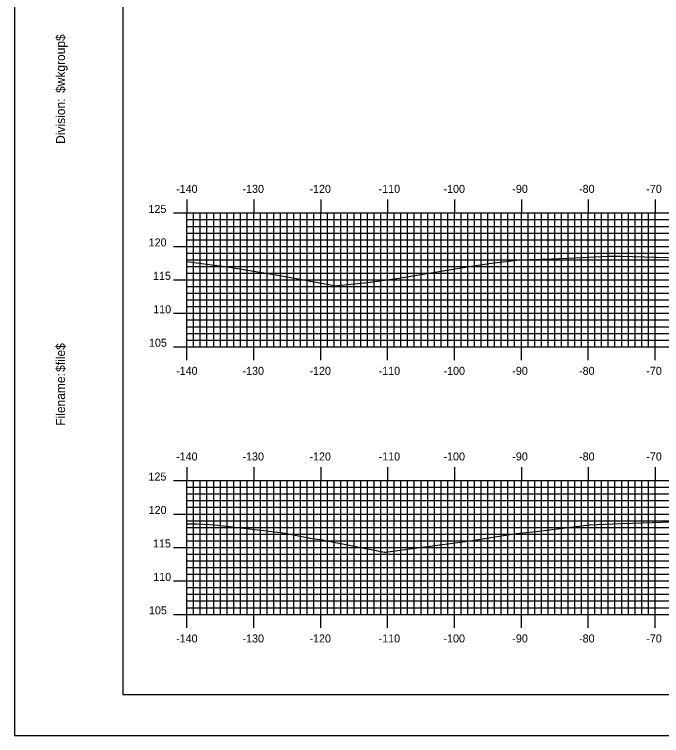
# Model space of a CAD drawing. Extents: x 844930 to 845273, y 363538 to 363758.
# Drawn here: x 844929.7 to 845026.4, y 363537.6 to 363645.4 of the extents above; entities that cross this region are included whole.
import ezdxf

# ---------------------------------------------------------------- set-up
doc = ezdxf.new("R2010")
doc.units = 0
for name, color, linetype in [('BORDER', 7, 'Continuous'), ('H_V ANNOTATION', 7, 'Continuous'), ('M_Roadway_Centerline', 7, 'Continuous'), ('MAJOR', 7, 'Continuous'), ('MINOR', 7, 'Continuous'), ('PLOT BOUNDARY', 7, 'Continuous'), ('S_Roadway_Centerline', 7, 'Continuous')]:
    doc.layers.add(name, color=color, linetype=linetype)

msp = doc.modelspace()

# ---------------------------------------------------------------- linework, layer by layer
at = {"layer": 'BORDER'}
msp.add_lwpolyline([(844945.88, 363543.72), (845265.88, 363543.72), (845265.88, 363753.72), (844945.88, 363753.72)], close=True, dxfattribs=at)
at = {"layer": 'MAJOR'}
for p, q in [((844955.48, 363617.73), (844955.48, 363615.72)), ((844965.48, 363617.73), (844965.48, 363615.72)), ((844975.48, 363617.73), (844975.48, 363615.72)), ((844985.48, 363617.73), (844985.48, 363615.72)), ((844995.48, 363617.73), (844995.48, 363615.72)), ((845005.48, 363617.73), (845005.48, 363615.72)), ((845015.48, 363617.73), (845015.48, 363615.72)), ((845025.48, 363617.73), (845025.48, 363615.72)), ((844953.47, 363615.72), (844955.48, 363615.72)), ((844955.48, 363615.72), (845235.48, 363615.72)), ((844955.48, 363595.72), (844955.48, 363615.72)), ((844955.48, 363595.72), (844955.48, 363615.72)), ((844955.48, 363615.72), (845235.48, 363615.72)), ((844965.48, 363595.72), (844965.48, 363615.72)), ((844975.48, 363595.72), (844975.48, 363615.72)), ((844985.48, 363595.72), (844985.48, 363615.72)), ((844995.48, 363595.72), (844995.48, 363615.72)), ((845005.48, 363595.72), (845005.48, 363615.72)), ((845015.48, 363595.72), (845015.48, 363615.72)), ((845025.48, 363595.72), (845025.48, 363615.72)), ((844953.47, 363610.72), (844955.48, 363610.72)), ((844955.48, 363610.72), (845235.48, 363610.72)), ((844953.47, 363605.72), (844955.48, 363605.72)), ((844955.48, 363605.72), (845235.48, 363605.72)), ((844953.47, 363600.72), (844955.48, 363600.72)), ((844955.48, 363600.72), (845235.48, 363600.72)), ((844953.47, 363595.72), (844955.48, 363595.72)), ((844955.48, 363595.72), (845235.48, 363595.72)), ((844955.48, 363595.72), (845235.48, 363595.72)), ((844955.48, 363593.72), (844955.48, 363595.72)), ((844965.48, 363593.72), (844965.48, 363595.72)), ((844975.48, 363593.72), (844975.48, 363595.72)), ((844985.48, 363593.72), (844985.48, 363595.72)), ((844995.48, 363593.72), (844995.48, 363595.72)), ((845005.48, 363593.72), (845005.48, 363595.72)), ((845015.48, 363593.72), (845015.48, 363595.72)), ((845025.48, 363593.72), (845025.48, 363595.72)), ((844955.48, 363577.73), (844955.48, 363575.72)), ((844965.48, 363577.73), (844965.48, 363575.72)), ((844975.48, 363577.73), (844975.48, 363575.72)), ((844985.48, 363577.73), (844985.48, 363575.72)), ((844995.48, 363577.73), (844995.48, 363575.72)), ((845005.48, 363577.73), (845005.48, 363575.72)), ((845015.48, 363577.73), (845015.48, 363575.72)), ((845025.48, 363577.73), (845025.48, 363575.72)), ((844953.47, 363575.72), (844955.48, 363575.72)), ((844955.48, 363575.72), (845235.48, 363575.72)), ((844955.48, 363555.72), (844955.48, 363575.72)), ((844955.48, 363555.72), (844955.48, 363575.72)), ((844955.48, 363575.72), (845235.48, 363575.72)), ((844965.48, 363555.72), (844965.48, 363575.72)), ((844975.48, 363555.72), (844975.48, 363575.72)), ((844985.48, 363555.72), (844985.48, 363575.72)), ((844995.48, 363555.72), (844995.48, 363575.72)), ((845005.48, 363555.72), (845005.48, 363575.72)), ((845015.48, 363555.72), (845015.48, 363575.72)), ((845025.48, 363555.72), (845025.48, 363575.72)), ((844953.47, 363570.72), (844955.48, 363570.72)), ((844955.48, 363570.72), (845235.48, 363570.72)), ((844953.47, 363565.72), (844955.48, 363565.72)), ((844955.48, 363565.72), (845235.48, 363565.72)), ((844953.47, 363560.72), (844955.48, 363560.72)), ((844955.48, 363560.72), (845235.48, 363560.72)), ((844953.47, 363555.72), (844955.48, 363555.72)), ((844955.48, 363555.72), (845235.48, 363555.72)), ((844955.48, 363555.72), (845235.48, 363555.72)), ((844955.48, 363553.72), (844955.48, 363555.72)), ((844965.48, 363553.72), (844965.48, 363555.72)), ((844975.48, 363553.72), (844975.48, 363555.72)), ((844985.48, 363553.72), (844985.48, 363555.72)), ((844995.48, 363553.72), (844995.48, 363555.72)), ((845005.48, 363553.72), (845005.48, 363555.72)), ((845015.48, 363553.72), (845015.48, 363555.72)), ((845025.48, 363553.72), (845025.48, 363555.72))]:
    msp.add_line(p, q, dxfattribs=at)
at = {"layer": 'MINOR'}
for p, q in [((844956.48, 363595.72), (844956.48, 363615.72)), ((844957.48, 363595.72), (844957.48, 363615.72)), ((844958.48, 363595.72), (844958.48, 363615.72)), ((844959.48, 363595.72), (844959.48, 363615.72)), ((844960.48, 363595.72), (844960.48, 363615.72)), ((844961.48, 363595.72), (844961.48, 363615.72)), ((844962.48, 363595.72), (844962.48, 363615.72)), ((844963.48, 363595.72), (844963.48, 363615.72)), ((844964.48, 363595.72), (844964.48, 363615.72)), ((844966.48, 363595.72), (844966.48, 363615.72)), ((844967.48, 363595.72), (844967.48, 363615.72)), ((844968.48, 363595.72), (844968.48, 363615.72)), ((844969.48, 363595.72), (844969.48, 363615.72)), ((844970.48, 363595.72), (844970.48, 363615.72)), ((844971.48, 363595.72), (844971.48, 363615.72)), ((844972.48, 363595.72), (844972.48, 363615.72)), ((844973.48, 363595.72), (844973.48, 363615.72)), ((844974.48, 363595.72), (844974.48, 363615.72)), ((844976.48, 363595.72), (844976.48, 363615.72)), ((844977.48, 363595.72), (844977.48, 363615.72)), ((844978.48, 363595.72), (844978.48, 363615.72)), ((844979.48, 363595.72), (844979.48, 363615.72)), ((844980.48, 363595.72), (844980.48, 363615.72)), ((844981.48, 363595.72), (844981.48, 363615.72)), ((844982.48, 363595.72), (844982.48, 363615.72)), ((844983.48, 363595.72), (844983.48, 363615.72)), ((844984.48, 363595.72), (844984.48, 363615.72)), ((844986.48, 363595.72), (844986.48, 363615.72)), ((844987.48, 363595.72), (844987.48, 363615.72)), ((844988.48, 363595.72), (844988.48, 363615.72)), ((844989.48, 363595.72), (844989.48, 363615.72)), ((844990.48, 363595.72), (844990.48, 363615.72)), ((844991.48, 363595.72), (844991.48, 363615.72)), ((844992.48, 363595.72), (844992.48, 363615.72)), ((844993.48, 363595.72), (844993.48, 363615.72)), ((844994.48, 363595.72), (844994.48, 363615.72)), ((844996.48, 363595.72), (844996.48, 363615.72)), ((844997.48, 363595.72), (844997.48, 363615.72)), ((844998.48, 363595.72), (844998.48, 363615.72)), ((844999.48, 363595.72), (844999.48, 363615.72)), ((845000.48, 363595.72), (845000.48, 363615.72)), ((845001.48, 363595.72), (845001.48, 363615.72)), ((845002.48, 363595.72), (845002.48, 363615.72)), ((845003.48, 363595.72), (845003.48, 363615.72)), ((845004.48, 363595.72), (845004.48, 363615.72)), ((845006.48, 363595.72), (845006.48, 363615.72)), ((845007.48, 363595.72), (845007.48, 363615.72)), ((845008.48, 363595.72), (845008.48, 363615.72)), ((845009.48, 363595.72), (845009.48, 363615.72)), ((845010.48, 363595.72), (845010.48, 363615.72)), ((845011.48, 363595.72), (845011.48, 363615.72)), ((845012.48, 363595.72), (845012.48, 363615.72)), ((845013.48, 363595.72), (845013.48, 363615.72)), ((845014.48, 363595.72), (845014.48, 363615.72)), ((845016.48, 363595.72), (845016.48, 363615.72)), ((845017.48, 363595.72), (845017.48, 363615.72)), ((845018.48, 363595.72), (845018.48, 363615.72)), ((845019.48, 363595.72), (845019.48, 363615.72)), ((845020.48, 363595.72), (845020.48, 363615.72)), ((845021.48, 363595.72), (845021.48, 363615.72)), ((845022.48, 363595.72), (845022.48, 363615.72)), ((845023.48, 363595.72), (845023.48, 363615.72)), ((845024.48, 363595.72), (845024.48, 363615.72)), ((844955.48, 363614.72), (845235.48, 363614.72)), ((844955.48, 363614.72), (844957.48, 363614.72)), ((844955.48, 363613.72), (845235.48, 363613.72)), ((844955.48, 363613.72), (844957.48, 363613.72)), ((844955.48, 363612.72), (845235.48, 363612.72)), ((844955.48, 363612.72), (844957.48, 363612.72)), ((844955.48, 363611.72), (845235.48, 363611.72)), ((844955.48, 363611.72), (844957.48, 363611.72)), ((844955.48, 363609.72), (845235.48, 363609.72)), ((844955.48, 363609.72), (844957.48, 363609.72)), ((844955.48, 363608.72), (845235.48, 363608.72)), ((844955.48, 363608.72), (844957.48, 363608.72)), ((844955.48, 363607.72), (845235.48, 363607.72)), ((844955.48, 363607.72), (844957.48, 363607.72)), ((844955.48, 363606.72), (845235.48, 363606.72)), ((844955.48, 363606.72), (844957.48, 363606.72)), ((844955.48, 363604.72), (845235.48, 363604.72)), ((844955.48, 363604.72), (844957.48, 363604.72)), ((844955.48, 363603.72), (845235.48, 363603.72)), ((844955.48, 363603.72), (844957.48, 363603.72)), ((844955.48, 363602.72), (845235.48, 363602.72)), ((844955.48, 363602.72), (844957.48, 363602.72)), ((844955.48, 363601.72), (845235.48, 363601.72)), ((844955.48, 363601.72), (844957.48, 363601.72)), ((844955.48, 363599.72), (845235.48, 363599.72)), ((844955.48, 363599.72), (844957.48, 363599.72)), ((844955.48, 363598.72), (845235.48, 363598.72)), ((844955.48, 363598.72), (844957.48, 363598.72)), ((844955.48, 363597.72), (845235.48, 363597.72)), ((844955.48, 363597.72), (844957.48, 363597.72)), ((844955.48, 363596.72), (845235.48, 363596.72)), ((844955.48, 363596.72), (844957.48, 363596.72)), ((844956.48, 363555.72), (844956.48, 363575.72)), ((844957.48, 363555.72), (844957.48, 363575.72)), ((844958.48, 363555.72), (844958.48, 363575.72)), ((844959.48, 363555.72), (844959.48, 363575.72)), ((844960.48, 363555.72), (844960.48, 363575.72)), ((844961.48, 363555.72), (844961.48, 363575.72)), ((844962.48, 363555.72), (844962.48, 363575.72)), ((844963.48, 363555.72), (844963.48, 363575.72)), ((844964.48, 363555.72), (844964.48, 363575.72)), ((844966.48, 363555.72), (844966.48, 363575.72)), ((844967.48, 363555.72), (844967.48, 363575.72)), ((844968.48, 363555.72), (844968.48, 363575.72)), ((844969.48, 363555.72), (844969.48, 363575.72)), ((844970.48, 363555.72), (844970.48, 363575.72)), ((844971.48, 363555.72), (844971.48, 363575.72)), ((844972.48, 363555.72), (844972.48, 363575.72)), ((844973.48, 363555.72), (844973.48, 363575.72)), ((844974.48, 363555.72), (844974.48, 363575.72)), ((844976.48, 363555.72), (844976.48, 363575.72)), ((844977.48, 363555.72), (844977.48, 363575.72)), ((844978.48, 363555.72), (844978.48, 363575.72)), ((844979.48, 363555.72), (844979.48, 363575.72)), ((844980.48, 363555.72), (844980.48, 363575.72)), ((844981.48, 363555.72), (844981.48, 363575.72)), ((844982.48, 363555.72), (844982.48, 363575.72)), ((844983.48, 363555.72), (844983.48, 363575.72)), ((844984.48, 363555.72), (844984.48, 363575.72)), ((844986.48, 363555.72), (844986.48, 363575.72)), ((844987.48, 363555.72), (844987.48, 363575.72)), ((844988.48, 363555.72), (844988.48, 363575.72)), ((844989.48, 363555.72), (844989.48, 363575.72)), ((844990.48, 363555.72), (844990.48, 363575.72)), ((844991.48, 363555.72), (844991.48, 363575.72)), ((844992.48, 363555.72), (844992.48, 363575.72)), ((844993.48, 363555.72), (844993.48, 363575.72)), ((844994.48, 363555.72), (844994.48, 363575.72)), ((844996.48, 363555.72), (844996.48, 363575.72)), ((844997.48, 363555.72), (844997.48, 363575.72)), ((844998.48, 363555.72), (844998.48, 363575.72)), ((844999.48, 363555.72), (844999.48, 363575.72)), ((845000.48, 363555.72), (845000.48, 363575.72)), ((845001.48, 363555.72), (845001.48, 363575.72)), ((845002.48, 363555.72), (845002.48, 363575.72)), ((845003.48, 363555.72), (845003.48, 363575.72)), ((845004.48, 363555.72), (845004.48, 363575.72)), ((845006.48, 363555.72), (845006.48, 363575.72)), ((845007.48, 363555.72), (845007.48, 363575.72)), ((845008.48, 363555.72), (845008.48, 363575.72)), ((845009.48, 363555.72), (845009.48, 363575.72)), ((845010.48, 363555.72), (845010.48, 363575.72)), ((845011.48, 363555.72), (845011.48, 363575.72)), ((845012.48, 363555.72), (845012.48, 363575.72)), ((845013.48, 363555.72), (845013.48, 363575.72)), ((845014.48, 363555.72), (845014.48, 363575.72)), ((845016.48, 363555.72), (845016.48, 363575.72)), ((845017.48, 363555.72), (845017.48, 363575.72)), ((845018.48, 363555.72), (845018.48, 363575.72)), ((845019.48, 363555.72), (845019.48, 363575.72)), ((845020.48, 363555.72), (845020.48, 363575.72)), ((845021.48, 363555.72), (845021.48, 363575.72)), ((845022.48, 363555.72), (845022.48, 363575.72)), ((845023.48, 363555.72), (845023.48, 363575.72)), ((845024.48, 363555.72), (845024.48, 363575.72)), ((844955.48, 363574.72), (845235.48, 363574.72)), ((844955.48, 363574.72), (844957.48, 363574.72)), ((844955.48, 363573.72), (845235.48, 363573.72)), ((844955.48, 363573.72), (844957.48, 363573.72)), ((844955.48, 363572.72), (845235.48, 363572.72)), ((844955.48, 363572.72), (844957.48, 363572.72)), ((844955.48, 363571.72), (845235.48, 363571.72)), ((844955.48, 363571.72), (844957.48, 363571.72)), ((844955.48, 363569.72), (845235.48, 363569.72)), ((844955.48, 363569.72), (844957.48, 363569.72)), ((844955.48, 363568.72), (845235.48, 363568.72)), ((844955.48, 363568.72), (844957.48, 363568.72)), ((844955.48, 363567.72), (845235.48, 363567.72)), ((844955.48, 363567.72), (844957.48, 363567.72)), ((844955.48, 363566.72), (845235.48, 363566.72)), ((844955.48, 363566.72), (844957.48, 363566.72)), ((844955.48, 363564.72), (845235.48, 363564.72)), ((844955.48, 363564.72), (844957.48, 363564.72)), ((844955.48, 363563.72), (845235.48, 363563.72)), ((844955.48, 363563.72), (844957.48, 363563.72)), ((844955.48, 363562.72), (845235.48, 363562.72)), ((844955.48, 363562.72), (844957.48, 363562.72)), ((844955.48, 363561.72), (845235.48, 363561.72)), ((844955.48, 363561.72), (844957.48, 363561.72)), ((844955.48, 363559.72), (845235.48, 363559.72)), ((844955.48, 363559.72), (844957.48, 363559.72)), ((844955.48, 363558.72), (845235.48, 363558.72)), ((844955.48, 363558.72), (844957.48, 363558.72)), ((844955.48, 363557.72), (845235.48, 363557.72)), ((844955.48, 363557.72), (844957.48, 363557.72)), ((844955.48, 363556.72), (845235.48, 363556.72)), ((844955.48, 363556.72), (844957.48, 363556.72))]:
    msp.add_line(p, q, dxfattribs=at)
at = {"layer": 'PLOT BOUNDARY'}
msp.add_lwpolyline([(844929.69, 363537.6), (845269.69, 363537.6), (845269.69, 363757.6), (844929.69, 363757.6)], close=True, dxfattribs=at)
at = {"layer": 'S_Roadway_Centerline'}
for points in [[(844955.48, 363608.45), (844959.22, 363607.98), (844961.91, 363607.64), (844969.69, 363606.31), (844977.76, 363604.82), (844977.99, 363604.86), (844982.53, 363605.31), (844987.14, 363605.99), (844997.36, 363607.69), (845000.67, 363608.14), (845005.21, 363608.69), (845010.01, 363608.88), (845014.59, 363609.06), (845018.44, 363609.25), (845020.28, 363609.26), (845027.48, 363609.04)], [(844955.48, 363569.27), (844956.97, 363569.23), (844959.63, 363569.11), (844969.05, 363568.01), (844970.15, 363567.86), (844973.9, 363567.12), (844975.7, 363566.87), (844985.01, 363565), (844985.18, 363565.04), (844990.66, 363565.76), (844997.49, 363566.66), (845004.69, 363567.8), (845007.69, 363568.13), (845015.21, 363569.05), (845015.63, 363569.1), (845015.69, 363569.11), (845019.18, 363569.24), (845027.98, 363569.56)]]:
    msp.add_lwpolyline(points, dxfattribs=at)

# ---------------------------------------------------------------- texts
at = {"layer": 'BORDER'}
for s, p in [('$wkgroup$', (844937.25, 363633.66)), ('Division:', (844937.25, 363626.05)), ('$file$', (844937.25, 363591.97)), ('Filename:', (844937.25, 363583.92))]:
    msp.add_text(s, height=1.339, rotation=90, dxfattribs=at).set_placement(p)
at = {"layer": 'H_V ANNOTATION'}
for s, p in [('-140', (844953.86, 363618.72)), ('-130', (844963.79, 363618.72)), ('-120', (844973.8, 363618.72)), ('-110', (844984.14, 363618.72)), ('-100', (844993.84, 363618.72)), ('-90', (845004.13, 363618.72)), ('-80', (845014.11, 363618.72)), ('-70', (845024.16, 363618.72)), ('125', (844949.73, 363615.72)), ('120', (844949.76, 363610.72)), ('115', (844950.41, 363605.72)), ('110', (844950.44, 363600.72)), ('105', (844949.81, 363595.72)), ('-140', (844953.86, 363591.52)), ('-130', (844963.79, 363591.52)), ('-120', (844973.8, 363591.52)), ('-110', (844984.14, 363591.52)), ('-100', (844993.84, 363591.52)), ('-90', (845004.13, 363591.52)), ('-80', (845014.11, 363591.52)), ('-70', (845024.16, 363591.52)), ('-140', (844953.86, 363578.72)), ('-130', (844963.79, 363578.72)), ('-120', (844973.8, 363578.72)), ('-110', (844984.14, 363578.72)), ('-100', (844993.84, 363578.72)), ('-90', (845004.13, 363578.72)), ('-80', (845014.11, 363578.72)), ('-70', (845024.16, 363578.72)), ('125', (844949.73, 363575.72)), ('120', (844949.76, 363570.72)), ('115', (844950.41, 363565.72)), ('110', (844950.44, 363560.72)), ('105', (844949.81, 363555.72)), ('-140', (844953.86, 363551.52)), ('-130', (844963.79, 363551.52)), ('-120', (844973.8, 363551.52)), ('-110', (844984.14, 363551.52)), ('-100', (844993.84, 363551.52)), ('-90', (845004.13, 363551.52)), ('-80', (845014.11, 363551.52)), ('-70', (845024.16, 363551.52))]:
    msp.add_text(s, height=1.2, dxfattribs=at).set_placement(p)
at = {"layer": 'M_Roadway_Centerline'}
for s, p in [('C', (845018.44, 363609.25)), ('L', (845018.44, 363609.24))]:
    msp.add_text(s, height=0.0146, dxfattribs=at).set_placement(p)
at = {"layer": 'MAJOR'}
for p in [(844955.47, 363595.72), (844955.47, 363555.72)]:
    msp.add_text('-', height=0.012, dxfattribs=at).set_placement(p)

doc.saveas('drawing.dxf')
